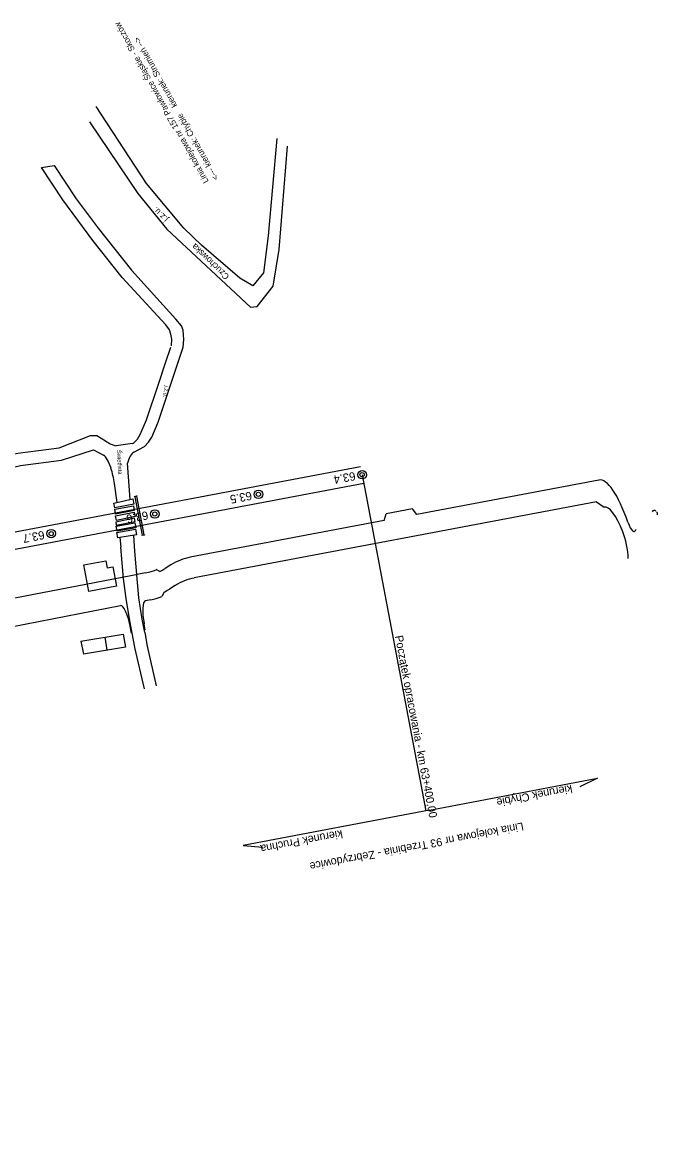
# Model space of a CAD drawing. Extents: x 6541740 to 6556805, y 5525233 to 5530361.
# Drawn here: x 6556654.1 to 6556804.7, y 5525917.2 to 5526183.1 of the extents above; entities that cross this region are included whole.
import ezdxf

# ---------------------------------------------------------------- set-up
doc = ezdxf.new("R2010")
doc.units = 0
for name, color, linetype in [('Default', 7, 'Continuous'), ('TOR_SCH-budynki', 7, 'Continuous'), ('TOR_SCH-hektometry', 7, 'Continuous'), ('TOR_SCH-obiekty istniejace', 7, 'Continuous'), ('TOR_SCH-opisy dodatkowe', 7, 'Continuous'), ('TOR_SCH-opisy glowne', 7, 'Continuous'), ('TOR_SCH-przejazdy+drogi istniejace', 7, 'Continuous'), ('TOR_SCH-przejazdy+drogi projektowane', 7, 'Continuous'), ('TOR_SCH-tory projektowane', 7, 'Continuous')]:
    doc.layers.add(name, color=color, linetype=linetype)

# ---------------------------------------------------------------- blocks, each defined once
blk = doc.blocks.new('4010_1')
at = {"layer": 'Default'}
for radius in [0.75, 0.375]:
    blk.add_circle((0, 0), radius, dxfattribs=at)

msp = doc.modelspace()

# ---------------------------------------------------------------- linework, layer by layer
at = {"layer": 'TOR_SCH-budynki'}
for p, q in [((6556668.71, 5526054.42), (6556673.88, 5526055.38)), ((6556673.88, 5526055.38), (6556674.19, 5526053.74)), ((6556669.86, 5526048.16), (6556668.71, 5526054.42)), ((6556674.19, 5526053.74), (6556675.59, 5526054)), ((6556675.59, 5526054), (6556676.46, 5526049.4)), ((6556676.46, 5526049.4), (6556669.86, 5526048.16)), ((6556668.01, 5526036.33), (6556678.01, 5526038.02)), ((6556668.01, 5526036.33), (6556668.57, 5526033.27)), ((6556673.63, 5526037.31), (6556674.16, 5526034.21)), ((6556678.01, 5526038.02), (6556678.53, 5526034.95)), ((6556678.53, 5526034.95), (6556668.57, 5526033.27))]:
    msp.add_line(p, q, dxfattribs=at)
at = {"layer": 'TOR_SCH-obiekty istniejace'}
for p, q in [((6556680.72, 5526070.67), (6556681.27, 5526070.81)), ((6556680.75, 5526070.57), (6556680.72, 5526070.67)), ((6556680.85, 5526070.6), (6556680.75, 5526070.57)), ((6556681.24, 5526070.72), (6556680.85, 5526070.6)), ((6556682.58, 5526061.5), (6556680.85, 5526070.6)), ((6556681.29, 5526070.73), (6556681.24, 5526070.72)), ((6556683, 5526061.58), (6556681.24, 5526070.72)), ((6556681.24, 5526070.72), (6556681.24, 5526070.72)), ((6556681.27, 5526070.81), (6556681.29, 5526070.73)), ((6556682.58, 5526061.5), (6556682.47, 5526061.48)), ((6556682.49, 5526061.4), (6556682.47, 5526061.48)), ((6556683.1, 5526061.51), (6556682.49, 5526061.4)), ((6556683, 5526061.58), (6556682.58, 5526061.5)), ((6556683, 5526061.58), (6556683.09, 5526061.6)), ((6556683.09, 5526061.6), (6556683.1, 5526061.51))]:
    msp.add_line(p, q, dxfattribs=at)
at = {"layer": 'TOR_SCH-opisy glowne'}
for p, q in [((6556734.63, 5526075.83), (6556749.74, 5525996.15)), ((6556750.64, 5525996.32), (6556790.44, 5526003.86)), ((6556790.44, 5526003.86), (6556786.22, 5526001.79)), ((6556750.64, 5525996.32), (6556706.43, 5525987.94)), ((6556706.43, 5525987.93), (6556711.12, 5525987.54))]:
    msp.add_line(p, q, dxfattribs=at)
at = {"layer": 'TOR_SCH-przejazdy+drogi istniejace'}
for p, q in [((6556683.56, 5526144.89), (6556671.58, 5526163.12)), ((6556670.03, 5526159.47), (6556681.52, 5526142.51)), ((6556714.43, 5526155.56), (6556712.37, 5526132.45)), ((6556714.95, 5526129.23), (6556716.97, 5526153.72)), ((6556658.68, 5526148.64), (6556661.68, 5526149.17)), ((6556663.7, 5526140.96), (6556658.68, 5526148.64)), ((6556661.68, 5526149.17), (6556666.87, 5526141.23)), ((6556692.38, 5526134.3), (6556683.56, 5526144.89)), ((6556670.84, 5526131.33), (6556663.7, 5526140.96)), ((6556666.87, 5526141.23), (6556672.05, 5526134.27)), ((6556681.52, 5526142.51), (6556688.37, 5526134.06)), ((6556672.05, 5526134.27), (6556680, 5526124.32)), ((6556688.37, 5526134.06), (6556708.16, 5526115.57)), ((6556696.57, 5526130.28), (6556692.38, 5526134.3)), ((6556712.37, 5526132.45), (6556711.28, 5526123.71)), ((6556677.76, 5526122.61), (6556670.84, 5526131.33)), ((6556705.63, 5526122.4), (6556696.57, 5526130.28)), ((6556713.53, 5526120.51), (6556714.95, 5526129.23)), ((6556680, 5526124.32), (6556690.51, 5526112.72)), ((6556688.15, 5526111.37), (6556677.76, 5526122.61)), ((6556708.74, 5526120.58), (6556705.63, 5526122.4)), ((6556711.28, 5526123.71), (6556708.74, 5526120.58)), ((6556709.77, 5526115.7), (6556713.53, 5526120.51)), ((6556708.16, 5526115.57), (6556709.77, 5526115.7)), ((6556680.2, 5526083.19), (6556676.38, 5526082.67)), ((6556679.63, 5526069.96), (6556679.05, 5526078.59)), ((6556676.61, 5526069.2), (6556675.94, 5526073.76)), ((6556677.22, 5526060.92), (6556677.47, 5526058.68)), ((6556680.75, 5526057.7), (6556680.54, 5526061.42)), ((6556683.13, 5526038.38), (6556683.72, 5526035.14)), ((6556683.03, 5526025.07), (6556680.78, 5526034.88)), ((6556683.72, 5526035.14), (6556685.85, 5526025.73))]:
    msp.add_line(p, q, dxfattribs=at)
for points in [[(6556689.43, 5526106.39), (6556689.54, 5526107.99), (6556689.33, 5526109.13), (6556688.97, 5526110.17), (6556688.15, 5526111.37)], [(6556692.24, 5526106.1), (6556692.37, 5526107.9), (6556692.19, 5526110.08), (6556691.83, 5526111.12), (6556690.51, 5526112.72)], [(6556680.5, 5526081.15), (6556683.04, 5526082.53), (6556684.01, 5526083.52), (6556684.8, 5526084.73), (6556686.27, 5526088.27), (6556689.25, 5526097.08), (6556692.24, 5526106.1)], [(6556688.08, 5526102.36), (6556689.32, 5526106.07)], [(6556680.2, 5526083.19), (6556680.48, 5526083.31), (6556681.4, 5526084.25), (6556682.03, 5526085.32), (6556683.5, 5526088.86), (6556686.48, 5526097.56), (6556688.08, 5526102.36)], [(6556634.04, 5526076.74), (6556653.08, 5526080.96), (6556662.87, 5526082.23), (6556670.25, 5526085.15), (6556671.73, 5526085.15), (6556673.8, 5526083.86)], [(6556634.74, 5526073.51), (6556653.64, 5526077.98), (6556663.43, 5526079.25), (6556670.97, 5526081.74), (6556670.97, 5526081.74), (6556673.35, 5526080.43)], [(6556680.78, 5526034.95), (6556679.61, 5526041.21), (6556678.74, 5526046.45), (6556678.1, 5526051.25), (6556677.47, 5526058.68)], [(6556683.13, 5526038.38), (6556682.53, 5526041.55), (6556681.69, 5526046.66), (6556681.37, 5526050.27), (6556680.75, 5526057.7)]]:
    msp.add_lwpolyline(points, dxfattribs=at)
for points in [[(6556675.83, 5526069.06), (6556680.28, 5526070.07), (6556680.52, 5526068.81), (6556676.05, 5526067.99)], [(6556676.01, 5526067.64), (6556680.43, 5526068.47), (6556680.65, 5526067.32), (6556676.21, 5526066.47)], [(6556676.18, 5526066.07), (6556680.62, 5526066.97), (6556680.85, 5526065.92), (6556676.4, 5526064.95)], [(6556680.69, 5526065.55), (6556676.24, 5526064.6), (6556676.33, 5526063.89), (6556680.82, 5526064.72)], [(6556676.34, 5526063.6), (6556680.81, 5526064.43), (6556681.01, 5526063.23), (6556676.55, 5526062.44)], [(6556676.49, 5526062.13), (6556680.95, 5526062.9), (6556681.18, 5526061.58), (6556676.72, 5526060.82)]]:
    msp.add_lwpolyline(points, close=True, dxfattribs=at)
for centre, radius, start, end in [((6556803.89, 5526066.87), 0.5, 40.9482, 160.4429), ((6556803.66, 5526066.38), 1, 355.1355, 40.9482)]:
    msp.add_arc(centre, radius, start, end, dxfattribs=at)
for centre, major_axis, ratio, start_param, end_param in [((6556666.51, 5526143.1), (-11.51, 60.45), 0.253017, 2.887468, 3.038362), ((6556674.28, 5526074.03), (1.23, -6.45), 0.25135, 2.063638, 2.965255), ((6556684.97, 5526060.38), (3.95, -20.98), 0.250361, 3.244551, 3.616048), ((6556674.06, 5526074.22), (1.32, -7.01), 0.248642, 1.459064, 1.987624)]:
    msp.add_ellipse(centre, major_axis=major_axis, ratio=ratio, start_param=start_param, end_param=end_param, dxfattribs=at)
at = {"layer": 'TOR_SCH-przejazdy+drogi projektowane'}
for p, q in [((6556790.78, 5526074.55), (6556747.57, 5526066.39)), ((6556790.22, 5526069.36), (6556694.85, 5526051.34)), ((6556790.22, 5526069.36), (6556791.97, 5526068.16)), ((6556739.87, 5526064.93), (6556740.32, 5526066.55)), ((6556746.55, 5526067.72), (6556740.32, 5526066.55)), ((6556747.57, 5526066.39), (6556746.55, 5526067.72)), ((6556739.87, 5526064.93), (6556693.92, 5526056.25)), ((6556683.34, 5526052.54), (6556679.79, 5526051.86)), ((6556686.71, 5526052.89), (6556685.85, 5526053.31)), ((6556689.32, 5526054.43), (6556687.94, 5526053.58)), ((6556679.79, 5526051.86), (6556569.29, 5526030.59)), ((6556687.7, 5526048), (6556687.15, 5526046.95)), ((6556690.37, 5526049.57), (6556688.99, 5526048.71)), ((6556570.53, 5526024.1), (6556677.39, 5526044.81)), ((6556684.55, 5526046.16), (6556683.27, 5526045.89)), ((6556679.97, 5526038.24), (6556679.65, 5526039.9)), ((6556683.23, 5526039.05), (6556682.96, 5526040.49))]:
    msp.add_line(p, q, dxfattribs=at)
for centre, major_axis, start_param, end_param in [((6556794.97, 5526052.45), (-4.19, 22.11), 5.2433, 6.283039), ((6556794.97, 5526052.45), (-2.98, 15.72), 5.336641, 6.288745), ((6556798.17, 5526067.53), (-0.98, 5.16), 2.140275, 3.570917), ((6556796.09, 5526058.67), (-0.98, 5.16), 4.109699, 5.428167), ((6556731.63, 5525857.29), (-37.71, 198.96), 6.283039, 6.379138), ((6556646.68, 5526245.85), (-36.64, 193.31), 3.141988, 3.195055), ((6556646.68, 5526245.85), (-36.78, 194.04), 3.210365, 3.237545), ((6556731.63, 5525857.29), (-36.78, 194.04), 6.283039, 6.379138), ((6556646.68, 5526245.85), (-37.71, 198.96), 3.209771, 3.237545), ((6556678.37, 5526039.65), (-0.98, 5.16), 4.713109, 6.283906), ((6556684.25, 5526040.74), (-0.98, 5.16), 0.000395, 1.571517), ((6556646.68, 5526245.85), (-37.85, 199.69), 3.141988, 3.195077)]:
    msp.add_ellipse(centre, major_axis=major_axis, ratio=0.25, start_param=start_param, end_param=end_param, dxfattribs=at)
at = {"layer": 'TOR_SCH-tory projektowane'}
for p, q in [((6556734.28, 5526077.71), (6556528.95, 5526038.79)), ((6556735.03, 5526073.73), (6555909.41, 5525917.23))]:
    msp.add_line(p, q, dxfattribs=at)

# ---------------------------------------------------------------- block references
at = {"layer": 'TOR_SCH-hektometry', "xscale": 1.345963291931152, "yscale": 1.345963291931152}
for p in [(6556734.63, 5526075.82), (6556710.07, 5526071.17), (6556685.51, 5526066.51), (6556660.95, 5526061.85)]:
    msp.add_blockref('4010_1', p, dxfattribs=at)

# ---------------------------------------------------------------- texts
at = {"layer": 'TOR_SCH-hektometry'}
for s, p in [('63.4', (6556732.86, 5526076.53)), ('63.5', (6556708.3, 5526071.87)), ('63.6', (6556683.74, 5526067.22)), ('63.7', (6556659.17, 5526062.56))]:
    msp.add_text(s, height=2, rotation=190.7691, dxfattribs=at).set_placement(p)
at = {"layer": 'TOR_SCH-opisy dodatkowe'}
for s, height, rotation, p in [('Linia kolejowa nr 157 Pawłowice Śląskie - Skoczów', 1.426, 119.2273, (6556698.33, 5526145.39)), ('kierunek: Strumień -->', 1.426, 119.2273, (6556690.88, 5526163.37)), ('<--- kierunek: Chybie', 1.4338, 119.5242, (6556700.69, 5526146.11))]:
    msp.add_text(s, height=height, rotation=rotation, dxfattribs=at).set_placement(p)
at = {"layer": 'TOR_SCH-opisy glowne'}
for s, rotation, p in [('Początek opracowania - km 63+400,00 ', 280.732, (6556742.41, 5526037.55)), ('kierunek Chybie', 190.732, (6556784.25, 5526002.34)), ('kierunek Pruchna', 190.732, (6556729.82, 5525991.64)), ('Linia kolejowa nr 93 Trzebinia - Zebrzydowice', 190.732, (6556772.72, 5525993.4))]:
    msp.add_text(s, height=1.9, rotation=rotation, dxfattribs=at).set_placement(p)
at = {"layer": 'TOR_SCH-przejazdy+drogi istniejace'}
for s, height, rotation, p in [('j.z.u.', 1.472, 134.7753, (6556688.81, 5526136.53)), ('Czuchowska', 1.491, 136.2833, (6556703.28, 5526122.97)), ('j.z.u.', 0.958, 258.5566, (6556687.95, 5526097)), ('Świetlista', 1, 273.1338, (6556676.52, 5526081.68))]:
    msp.add_text(s, height=height, rotation=rotation, dxfattribs=at).set_placement(p)

doc.saveas('drawing.dxf')
